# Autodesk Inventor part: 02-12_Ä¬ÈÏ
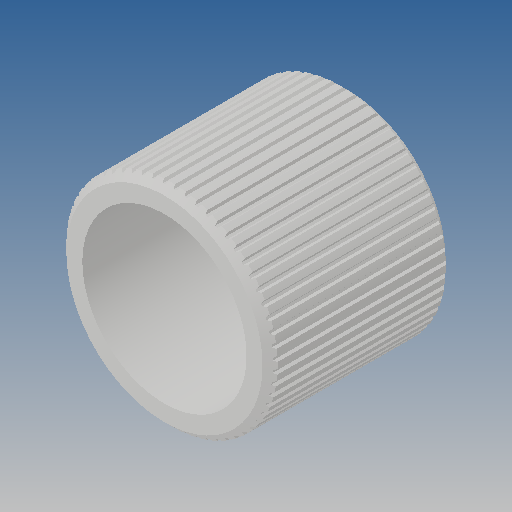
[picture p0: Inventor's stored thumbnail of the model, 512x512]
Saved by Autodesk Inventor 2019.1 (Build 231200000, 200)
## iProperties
Created: 2010-06
Part Number: 02-12_Ä¬ÈÏ
Material: Ogólny
Document SubType Name: Modeling
Designer: CADENGINEERING4
Density: 1 g/cm^3
Appearance: Domyślna
Author: CADENGINEERING4
Revision Number: ÈÎºÎ
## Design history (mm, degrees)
feature "NONE"
node "Bryła1"
